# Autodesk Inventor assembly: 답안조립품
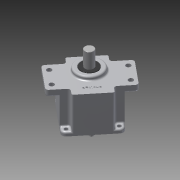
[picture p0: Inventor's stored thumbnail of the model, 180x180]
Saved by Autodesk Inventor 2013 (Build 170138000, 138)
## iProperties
Created: 2015-07
Part Number: 답안조립품
Document SubType Name: Assembly
Designer: user
Author: user
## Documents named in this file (11)
- C:\Users\user\Desktop\450734V1011\답안조립품.iam
- C:\Users\user\Desktop\450734V1011\메인축.ipt
- C:\Users\user\Desktop\450734V1011\서브축.ipt
- C:\Users\user\Desktop\450734V1011\베어링 6003.ipt
- 베어링 6003.ipt
- C:\Users\user\Desktop\450734V1011\베어링 608.ipt
- 베어링 608.ipt
- C:\Users\user\Desktop\450734V1011\본체.ipt
- C:\Users\user\Desktop\450734V1011\오일실 17x32x8.ipt
- C:\Users\user\Desktop\450734V1011\커버.ipt
- C:\Users\user\Desktop\450734V1011\M4x0.5x16.ipt
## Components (4 placed, 1 different names)
1. M4x0.5x12:1
2. M4x0.5x12:2
3. M4x0.5x12:3
4. M4x0.5x12:4
